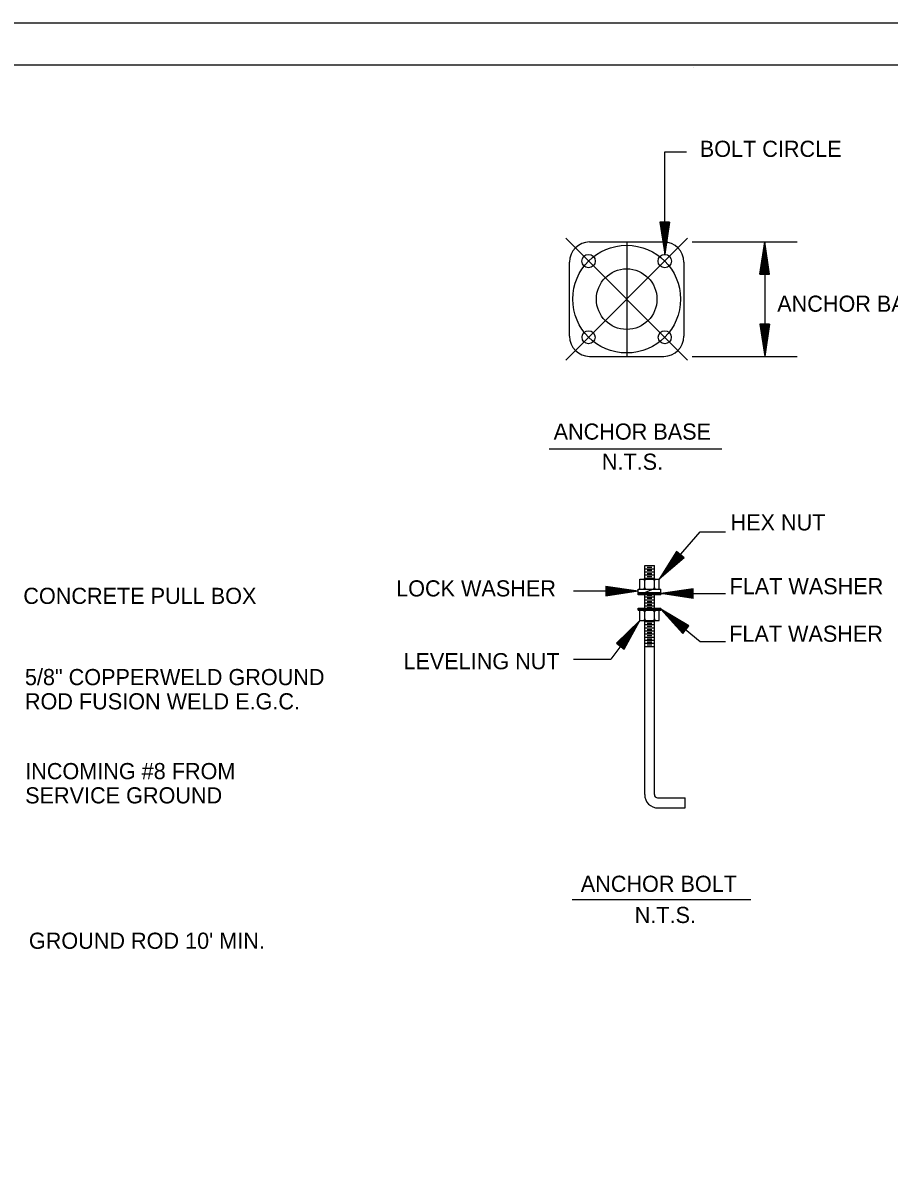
# Model space of a CAD drawing. Extents: x 1369885 to 1370886, y 379976 to 380616.
# Drawn here: x 1370193.7 to 1370434.9, y 380298 to 380615.6 of the extents above; entities that cross this region are included whole.
import ezdxf

# ---------------------------------------------------------------- set-up
doc = ezdxf.new("R2010")
doc.units = 0
for name, color, linetype in [('R_Border', 7, 'Continuous'), ('R_Draft', 7, 'Continuous'), ('R_No Plot', 7, 'Continuous')]:
    doc.layers.add(name, color=color, linetype=linetype)

msp = doc.modelspace()

# ---------------------------------------------------------------- linework, layer by layer
at = {"layer": 'R_Border'}
for p, q in [((1369922.71, 380603.9), (1370871.25, 380603.9)), ((1370380.27, 380603.12), (1370380.27, 380603.12)), ((1370380.27, 380603.12), (1370380.27, 380603.12))]:
    msp.add_line(p, q, dxfattribs=at)
at = {"layer": 'R_Draft'}
for p, q in [((1370372.41, 380551.11), (1370372.41, 380579.7)), ((1370372.41, 380579.7), (1370378.44, 380579.7)), ((1370371.06, 380560.11), (1370372.41, 380551.11)), ((1370373.76, 380560.11), (1370371.06, 380560.11)), ((1370371.28, 380560.11), (1370372.41, 380552.61)), ((1370371.51, 380560.11), (1370372.41, 380554.16)), ((1370371.73, 380560.11), (1370372.41, 380555.66)), ((1370371.96, 380560.11), (1370372.41, 380557.18)), ((1370372.19, 380560.11), (1370372.41, 380558.69)), ((1370373.76, 380560.11), (1370372.41, 380551.11)), ((1370372.84, 380560.11), (1370372.41, 380557.18)), ((1370373.3, 380560.11), (1370372.41, 380554.16)), ((1370373.53, 380560.11), (1370372.41, 380552.61)), ((1370373.08, 380560.11), (1370372.41, 380555.66)), ((1370372.62, 380560.11), (1370372.41, 380558.69)), ((1370378.77, 380521.66), (1370344.83, 380555.6)), ((1370344.83, 380521.66), (1370378.77, 380555.6)), ((1370351.49, 380554.56), (1370372.11, 380554.56)), ((1370361.8, 380554.56), (1370361.8, 380522.69)), ((1370379.99, 380554.56), (1370409.24, 380554.56)), ((1370398.89, 380545.56), (1370400.24, 380554.56)), ((1370399.11, 380545.56), (1370400.24, 380553.06)), ((1370400.24, 380554.56), (1370400.24, 380522.69)), ((1370401.59, 380545.56), (1370400.24, 380554.56)), ((1370401.36, 380545.56), (1370400.24, 380553.06)), ((1370345.86, 380528.31), (1370345.86, 380548.94)), ((1370377.74, 380548.94), (1370377.74, 380528.31)), ((1370399.34, 380545.56), (1370400.24, 380551.51)), ((1370399.57, 380545.56), (1370400.24, 380550.02)), ((1370401.13, 380545.56), (1370400.24, 380551.51)), ((1370400.91, 380545.56), (1370400.24, 380550.02)), ((1370398.89, 380545.56), (1370401.59, 380545.56)), ((1370399.8, 380545.56), (1370400.24, 380548.49)), ((1370400.02, 380545.56), (1370400.24, 380546.99)), ((1370400.68, 380545.56), (1370400.24, 380548.49)), ((1370400.45, 380545.56), (1370400.24, 380546.99)), ((1370398.89, 380531.69), (1370400.24, 380522.69)), ((1370401.59, 380531.69), (1370398.89, 380531.69)), ((1370399.11, 380531.69), (1370400.24, 380524.19)), ((1370399.34, 380531.69), (1370400.24, 380525.74)), ((1370399.57, 380531.69), (1370400.24, 380527.24)), ((1370399.79, 380531.69), (1370400.24, 380528.76)), ((1370400.02, 380531.69), (1370400.24, 380530.27)), ((1370401.59, 380531.69), (1370400.24, 380522.69)), ((1370400.67, 380531.69), (1370400.24, 380528.76)), ((1370401.13, 380531.69), (1370400.24, 380525.74)), ((1370401.36, 380531.69), (1370400.24, 380524.19)), ((1370400.91, 380531.69), (1370400.24, 380527.24)), ((1370400.45, 380531.69), (1370400.24, 380530.27)), ((1370351.49, 380522.69), (1370372.11, 380522.69)), ((1370379.99, 380522.69), (1370409.24, 380522.69)), ((1370388.32, 380496.88), (1370340.24, 380496.88)), ((1370370.86, 380460.67), (1370382.27, 380473.83)), ((1370382.27, 380473.83), (1370389.31, 380473.83)), ((1370375.71, 380468.36), (1370370.86, 380460.67)), ((1370377.76, 380466.6), (1370370.86, 380460.67)), ((1370375.88, 380468.22), (1370371.84, 380461.8)), ((1370377.59, 380466.75), (1370371.84, 380461.8)), ((1370376.06, 380468.07), (1370372.85, 380462.98)), ((1370377.41, 380466.9), (1370372.85, 380462.98)), ((1370376.23, 380467.92), (1370373.83, 380464.11)), ((1370377.24, 380467.04), (1370373.83, 380464.11)), ((1370376.4, 380467.77), (1370374.83, 380465.27)), ((1370377.07, 380467.2), (1370374.83, 380465.27)), ((1370377.76, 380466.6), (1370375.71, 380468.36)), ((1370376.58, 380467.62), (1370375.81, 380466.41)), ((1370376.9, 380467.34), (1370375.81, 380466.41)), ((1370366.81, 380464.42), (1370369.51, 380464.42)), ((1370366.81, 380460.67), (1370366.81, 380464.42)), ((1370366.81, 380463.55), (1370369.51, 380463.55)), ((1370367.48, 380463.97), (1370368.83, 380463.97)), ((1370367.48, 380463.1), (1370368.83, 380463.1)), ((1370369.51, 380460.67), (1370369.51, 380464.42)), ((1370365.46, 380457.82), (1370365.46, 380460.67)), ((1370365.46, 380460.67), (1370370.86, 380460.67)), ((1370366.81, 380462.69), (1370369.51, 380462.69)), ((1370366.81, 380461.82), (1370369.51, 380461.82)), ((1370366.81, 380460.95), (1370369.51, 380460.95)), ((1370366.81, 380457.82), (1370366.81, 380460.67)), ((1370367.48, 380462.24), (1370368.83, 380462.24)), ((1370367.48, 380461.37), (1370368.83, 380461.37)), ((1370369.51, 380457.82), (1370369.51, 380460.67)), ((1370370.86, 380457.82), (1370370.86, 380460.67)), ((1370347.01, 380457.37), (1370365.01, 380457.37)), ((1370356.01, 380458.72), (1370365.01, 380457.37)), ((1370356.01, 380458.72), (1370356.01, 380456.02)), ((1370356.01, 380458.5), (1370363.51, 380457.37)), ((1370356.01, 380458.27), (1370361.96, 380457.37)), ((1370356.01, 380458.04), (1370360.46, 380457.37)), ((1370356.01, 380457.81), (1370358.93, 380457.37)), ((1370356.01, 380457.58), (1370357.43, 380457.37)), ((1370356.01, 380456.02), (1370365.01, 380457.37)), ((1370356.01, 380456.93), (1370358.93, 380457.37)), ((1370356.01, 380456.48), (1370361.96, 380457.37)), ((1370356.01, 380456.25), (1370363.51, 380457.37)), ((1370356.01, 380456.7), (1370360.46, 380457.37)), ((1370356.01, 380457.16), (1370357.43, 380457.37)), ((1370365.01, 380456.32), (1370365.01, 380457.82)), ((1370365.01, 380457.82), (1370371.31, 380457.82)), ((1370365.01, 380456.92), (1370371.31, 380456.92)), ((1370365.01, 380456.35), (1370365.58, 380456.92)), ((1370365.01, 380456.67), (1370365.26, 380456.92)), ((1370365.3, 380456.32), (1370365.9, 380456.92)), ((1370365.61, 380456.32), (1370366.21, 380456.92)), ((1370365.93, 380456.32), (1370366.53, 380456.92)), ((1370366.25, 380456.32), (1370366.85, 380456.92)), ((1370366.57, 380456.32), (1370367.17, 380456.92)), ((1370366.82, 380456.92), (1370368.79, 380457.79)), ((1370366.89, 380456.32), (1370367.49, 380456.92)), ((1370367.21, 380456.32), (1370367.81, 380456.92)), ((1370367.52, 380456.32), (1370368.12, 380456.92)), ((1370367.84, 380456.32), (1370368.44, 380456.92)), ((1370368.16, 380456.32), (1370368.76, 380456.92)), ((1370368.48, 380456.32), (1370369.08, 380456.92)), ((1370368.8, 380456.32), (1370369.4, 380456.92)), ((1370369.11, 380456.32), (1370369.71, 380456.92)), ((1370369.43, 380456.32), (1370370.03, 380456.92)), ((1370369.75, 380456.32), (1370370.35, 380456.92)), ((1370370.07, 380456.32), (1370370.67, 380456.92)), ((1370370.39, 380456.32), (1370370.99, 380456.92)), ((1370370.71, 380456.32), (1370371.31, 380456.92)), ((1370380.31, 380457.97), (1370371.31, 380456.62)), ((1370371.31, 380456.32), (1370371.31, 380457.82)), ((1370371.31, 380456.62), (1370389.31, 380456.62)), ((1370380.31, 380455.27), (1370371.31, 380456.62)), ((1370380.31, 380457.74), (1370372.81, 380456.62)), ((1370380.31, 380455.49), (1370372.81, 380456.62)), ((1370380.31, 380457.52), (1370374.36, 380456.62)), ((1370380.31, 380455.72), (1370374.36, 380456.62)), ((1370380.31, 380457.29), (1370375.86, 380456.62)), ((1370380.31, 380455.95), (1370375.86, 380456.62)), ((1370380.31, 380457.06), (1370377.38, 380456.62)), ((1370380.31, 380456.18), (1370377.38, 380456.62)), ((1370380.31, 380456.83), (1370378.89, 380456.62)), ((1370380.31, 380456.41), (1370378.89, 380456.62)), ((1370380.31, 380455.27), (1370380.31, 380457.97)), ((1370371.31, 380456.32), (1370365.01, 380456.32)), ((1370366.81, 380452.57), (1370366.81, 380456.32)), ((1370366.81, 380455.76), (1370369.51, 380455.76)), ((1370366.81, 380454.9), (1370369.51, 380454.9)), ((1370366.81, 380454.03), (1370369.51, 380454.03)), ((1370367.48, 380456.18), (1370368.83, 380456.18)), ((1370367.48, 380455.31), (1370368.83, 380455.31)), ((1370367.48, 380454.45), (1370368.83, 380454.45)), ((1370367.48, 380453.58), (1370368.83, 380453.58)), ((1370369.51, 380452.57), (1370369.51, 380456.32)), ((1370371.02, 380456.32), (1370371.31, 380456.6)), ((1370365.01, 380451.97), (1370365.01, 380452.57)), ((1370365.01, 380452.57), (1370371.31, 380452.57)), ((1370365.01, 380452.27), (1370365.31, 380452.57)), ((1370365.01, 380451.97), (1370371.31, 380451.97)), ((1370365.03, 380451.97), (1370365.63, 380452.57)), ((1370365.35, 380451.97), (1370365.95, 380452.57)), ((1370365.46, 380449.13), (1370365.46, 380451.97)), ((1370365.67, 380451.97), (1370366.27, 380452.57)), ((1370365.99, 380451.97), (1370366.59, 380452.57)), ((1370366.3, 380451.97), (1370366.9, 380452.57)), ((1370366.62, 380451.97), (1370367.22, 380452.57)), ((1370366.81, 380453.17), (1370369.51, 380453.17)), ((1370366.81, 380449.13), (1370366.81, 380451.97)), ((1370366.94, 380451.97), (1370367.54, 380452.57)), ((1370367.26, 380451.97), (1370367.86, 380452.57)), ((1370367.48, 380452.72), (1370368.83, 380452.72)), ((1370367.58, 380451.97), (1370368.18, 380452.57)), ((1370367.89, 380451.97), (1370368.49, 380452.57)), ((1370368.21, 380451.97), (1370368.81, 380452.57)), ((1370368.53, 380451.97), (1370369.13, 380452.57)), ((1370368.85, 380451.97), (1370369.45, 380452.57)), ((1370369.17, 380451.97), (1370369.77, 380452.57)), ((1370369.49, 380451.97), (1370370.09, 380452.57)), ((1370369.51, 380449.13), (1370369.51, 380451.97)), ((1370369.8, 380451.97), (1370370.4, 380452.57)), ((1370370.12, 380451.97), (1370370.72, 380452.57)), ((1370370.44, 380451.97), (1370371.04, 380452.57)), ((1370370.76, 380451.97), (1370371.31, 380452.52)), ((1370370.86, 380449.13), (1370370.86, 380451.97)), ((1370371.08, 380451.97), (1370371.31, 380452.2)), ((1370371.31, 380451.97), (1370371.31, 380452.57)), ((1370371.31, 380452.27), (1370382.27, 380443.24)), ((1370377.4, 380445.51), (1370371.31, 380452.27)), ((1370379.12, 380447.6), (1370371.31, 380452.27)), ((1370377.55, 380445.68), (1370372.47, 380451.32)), ((1370378.97, 380447.42), (1370372.47, 380451.32)), ((1370378.83, 380447.24), (1370373.67, 380450.33)), ((1370377.69, 380445.86), (1370373.67, 380450.33)), ((1370365.46, 380449.13), (1370357.41, 380438.33)), ((1370358.93, 380442.78), (1370365.46, 380449.13)), ((1370359.11, 380442.65), (1370364.55, 380447.93)), ((1370360.9, 380441.29), (1370364.55, 380447.93)), ((1370361.08, 380441.15), (1370365.46, 380449.13)), ((1370365.46, 380449.13), (1370370.86, 380449.13)), ((1370366.81, 380400.67), (1370366.81, 380449.13)), ((1370366.81, 380448.84), (1370369.51, 380448.84)), ((1370366.81, 380447.97), (1370369.51, 380447.97)), ((1370366.81, 380447.11), (1370369.51, 380447.11)), ((1370367.48, 380448.39), (1370368.83, 380448.39)), ((1370367.48, 380447.52), (1370368.83, 380447.52)), ((1370369.51, 380400.63), (1370369.51, 380449.13)), ((1370377.83, 380446.04), (1370374.82, 380449.38)), ((1370378.69, 380447.07), (1370374.82, 380449.38)), ((1370378.54, 380446.89), (1370376, 380448.41)), ((1370377.98, 380446.22), (1370376, 380448.41)), ((1370378.39, 380446.72), (1370377.16, 380447.46)), ((1370378.13, 380446.39), (1370377.16, 380447.46)), ((1370377.4, 380445.51), (1370379.12, 380447.6)), ((1370359.29, 380442.51), (1370363.61, 380446.7)), ((1370359.47, 380442.37), (1370362.7, 380445.51)), ((1370359.66, 380442.23), (1370361.78, 380444.29)), ((1370360.36, 380441.7), (1370361.78, 380444.29)), ((1370360.54, 380441.56), (1370362.7, 380445.51)), ((1370360.72, 380441.42), (1370363.61, 380446.7)), ((1370366.81, 380446.24), (1370369.51, 380446.24)), ((1370366.81, 380445.38), (1370369.51, 380445.38)), ((1370366.81, 380444.51), (1370369.51, 380444.51)), ((1370367.48, 380446.66), (1370368.83, 380446.66)), ((1370367.48, 380445.79), (1370368.83, 380445.79)), ((1370367.48, 380444.93), (1370368.83, 380444.93)), ((1370367.48, 380444.06), (1370368.83, 380444.06)), ((1370358.93, 380442.78), (1370361.08, 380441.15)), ((1370359.84, 380442.09), (1370360.87, 380443.1)), ((1370360.17, 380441.84), (1370360.87, 380443.1)), ((1370366.81, 380443.65), (1370369.51, 380443.65)), ((1370366.81, 380442.78), (1370369.51, 380442.78)), ((1370366.81, 380441.92), (1370369.51, 380441.92)), ((1370367.48, 380443.2), (1370368.83, 380443.2)), ((1370367.48, 380442.33), (1370368.83, 380442.33)), ((1370382.27, 380443.24), (1370389.31, 380443.24)), ((1370347.01, 380438.33), (1370357.41, 380438.33)), ((1370370.41, 380399.73), (1370378.06, 380399.73)), ((1370378.06, 380396.92), (1370378.06, 380399.73)), ((1370370.56, 380396.92), (1370378.06, 380396.92)), ((1370396.38, 380371.32), (1370346.65, 380371.32))]:
    msp.add_line(p, q, dxfattribs=at)
for centre, radius in [((1370361.8, 380538.63), 15), ((1370351.19, 380549.23), 1.87), ((1370372.41, 380549.23), 1.87), ((1370361.8, 380538.63), 8.44), ((1370351.19, 380528.02), 1.8), ((1370372.41, 380528.02), 1.8)]:
    msp.add_circle(centre, radius, dxfattribs=at)
for centre, radius, start, end in [((1370351.49, 380548.94), 5.62, 90, 180), ((1370372.11, 380548.94), 5.62, 360, 90), ((1370351.49, 380528.31), 5.62, 180, 270), ((1370372.11, 380528.31), 5.62, 270, 0), ((1370366.36, 380460.22), 0.45, 0, 90), ((1370367.26, 380460.22), 0.45, 90, 180), ((1370369.06, 380460.22), 0.45, 0, 90), ((1370369.96, 380460.22), 0.45, 90, 180), ((1370366.36, 380458.27), 0.45, 270, 0), ((1370367.26, 380458.27), 0.45, 180, 270), ((1370369.06, 380458.27), 0.45, 270, 0), ((1370369.96, 380458.27), 0.45, 180, 270), ((1370366.36, 380451.52), 0.45, 0, 90), ((1370367.26, 380451.52), 0.45, 90, 180), ((1370369.06, 380451.52), 0.45, 0, 90), ((1370369.96, 380451.52), 0.45, 90, 180), ((1370366.36, 380449.58), 0.45, 270, 0), ((1370367.26, 380449.58), 0.45, 180, 270), ((1370369.06, 380449.58), 0.45, 270, 0), ((1370369.96, 380449.58), 0.45, 180, 270), ((1370370.56, 380400.67), 3.75, 180, 270), ((1370370.41, 380400.63), 0.9, 180, 270)]:
    msp.add_arc(centre, radius, start, end, dxfattribs=at)
at = {"layer": 'R_No Plot'}
msp.add_line((1369885.51, 380615.59), (1370885.51, 380615.59), dxfattribs=at)
msp.add_lwpolyline([(1369885.49, 380615.59), (1370885.51, 380615.59), (1370885.51, 379975.58), (1369885.49, 379975.58)], close=True, dxfattribs=at)

# ---------------------------------------------------------------- texts
at = {"layer": 'R_Draft'}
for s, p in [('BOLT CIRCLE', (1370382.15, 380578.25)), ('ANCHOR BASE SQUARE', (1370403.7, 380535.11)), ('ANCHOR BASE', (1370341.47, 380499.49)), ('N.T.S.', (1370354.9, 380491.1)), ('HEX NUT', (1370390.7, 380474.21)), ('LOCK WASHER', (1370297.64, 380455.82)), ('FLAT WASHER', (1370390.43, 380456.43)), ('CONCRETE PULL BOX', (1370193.87, 380453.74)), ('FLAT WASHER', (1370390.33, 380443.19)), ('LEVELING NUT', (1370299.66, 380435.54)), ('5/8" COPPERWELD GROUND ', (1370194.31, 380431.12)), ('ROD FUSION WELD E.G.C.', (1370194.31, 380424.37)), ('INCOMING #8 FROM ', (1370194.39, 380404.93)), ('SERVICE GROUND', (1370194.39, 380398.18)), ('ANCHOR BOLT', (1370349.03, 380373.55)), ('N.T.S.', (1370364.04, 380364.87)), ("GROUND ROD 10' MIN.", (1370195.43, 380357.69))]:
    msp.add_text(s, height=4.5, dxfattribs=at).set_placement(p)

doc.saveas('drawing.dxf')
